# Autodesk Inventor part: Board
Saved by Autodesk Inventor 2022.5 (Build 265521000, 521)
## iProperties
Created: 2025-02
Part Number: Board
Material: Generic
Document SubType Name: Modeling
Designer: AdminForWorker
Density: 1 g/cm^3
Appearance: Default
Title: Board
Author: AdminForWorker
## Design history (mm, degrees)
feature "Board"
feature "CopperHoles"
body "Solid1"
body "Solid2"
